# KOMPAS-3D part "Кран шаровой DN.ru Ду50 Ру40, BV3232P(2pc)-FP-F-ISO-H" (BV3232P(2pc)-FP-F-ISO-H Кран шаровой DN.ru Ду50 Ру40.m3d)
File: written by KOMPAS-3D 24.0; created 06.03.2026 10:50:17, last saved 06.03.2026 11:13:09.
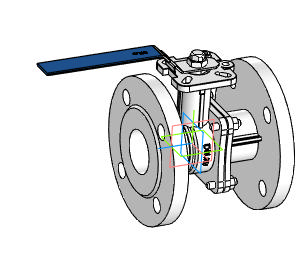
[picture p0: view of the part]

Document properties: Автор: R2D2; Полное имя файла: E:\Работа\Зайцев\BV3232P(2pc)-FP-F-ISO-H Кран шаровой DN.ru Ду15-300 Ру16-40\DN50 PN40\BV3232P(2pc)-FP-F-ISO-H Кран шаровой DN.ru Ду50 Ру40.m3d

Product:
- Part/product: Кран шаровой DN.ru Ду50 Ру40  | designation BV3232P(2pc)-FP-F-ISO-H
    Масса: 8.78
    Раздел спецификации: Прочие изделия
    Форматы листов документа: A2
    Примечание: D160-22134

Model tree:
1. Операция без истории:1

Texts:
  BV3232P(2pc)-FP-F-ISO-H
